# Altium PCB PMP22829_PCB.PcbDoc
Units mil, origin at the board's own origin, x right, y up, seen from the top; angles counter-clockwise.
Board outline 1149 x 492 mil, 4 copper layers (Top Layer, Signal Layer 1, Signal Layer 2, Bottom Layer), stack 61.2 mil thick; 29 components, 17 nets, 67 pads, 32 vias.
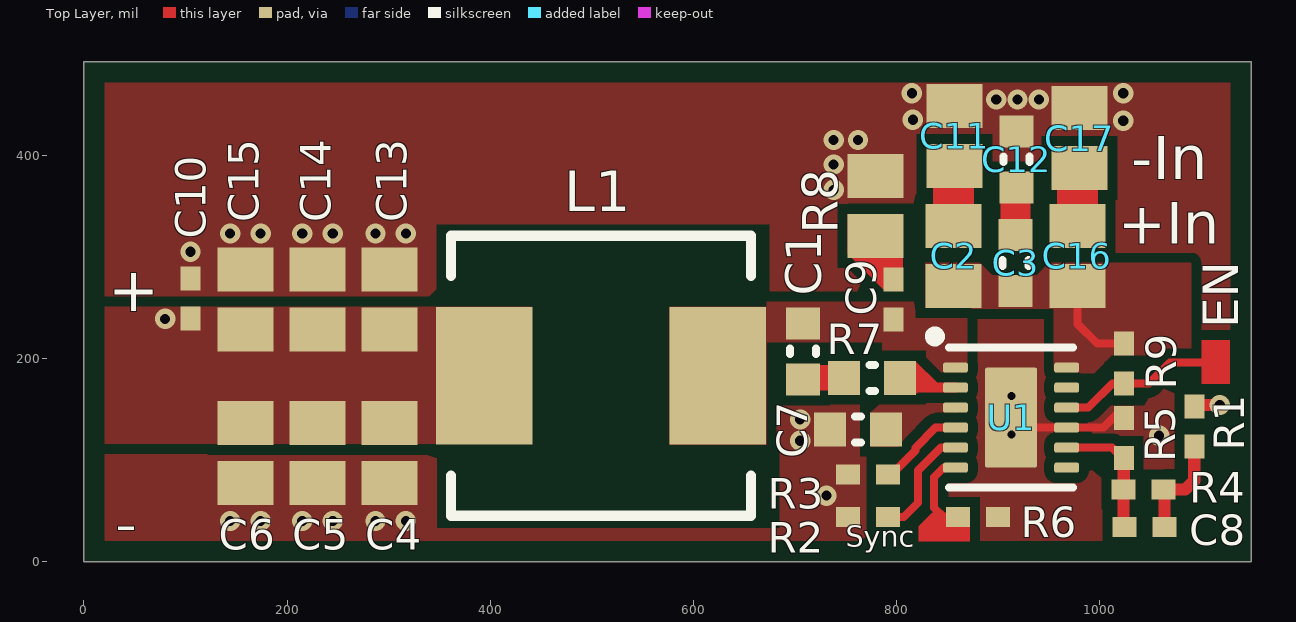
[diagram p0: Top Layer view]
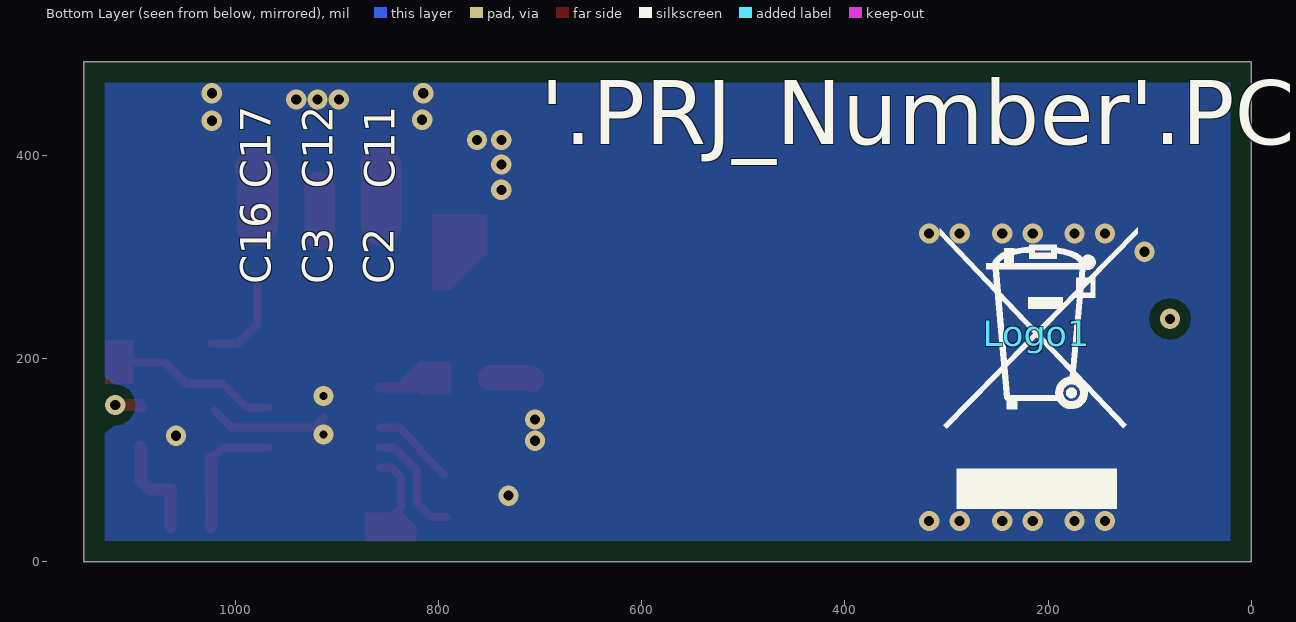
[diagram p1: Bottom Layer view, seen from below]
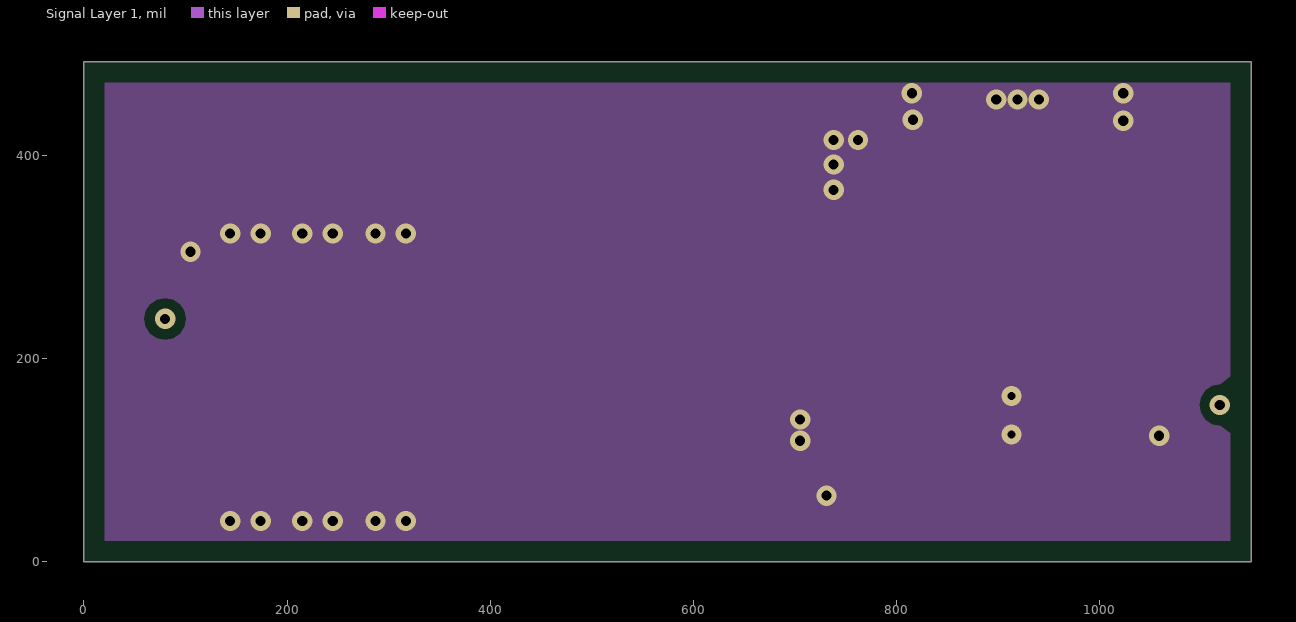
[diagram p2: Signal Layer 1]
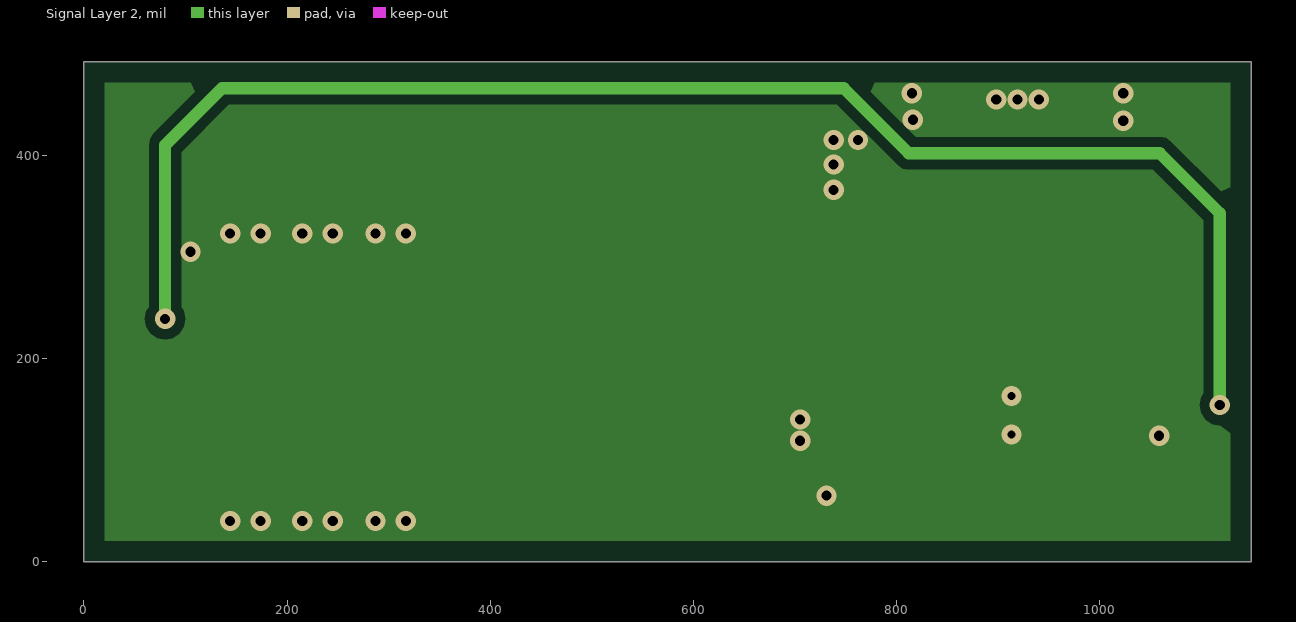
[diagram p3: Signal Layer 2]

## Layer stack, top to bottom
Top Solder: solder mask 0.4, Solder Resist, Dk 3.5
Top Layer: signal copper 1.4
Dielectric 2: dielectric 7.8, Dk 4.2
Signal Layer 1: signal copper 1.4
Dielectric1: core 40, FR-4, Dk 4.8
Signal Layer 2: signal copper 1.4
Dielectric 3: dielectric 7.8, Dk 4.2
Bottom Layer: signal copper 1.4
Bottom Solder: solder mask 0.4, Solder Resist, Dk 3.5

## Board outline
0,0 1149,0 1149,492 0,492

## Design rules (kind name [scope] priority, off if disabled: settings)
AcuteAngle [All] p1: minimum=4.50000000000000E+0001 checktracksonly=FALSE
AssemblyTestPointUsage [All] p1: valid=2
BoardOutlineClearance BoardOutlineClearance_MountingHoles [OnCopper and InComponentClass('Mounting Holes')] p1: gap=39.37 ignorepadtopadclearanceinfootprint=FALSE
BoardOutlineClearance BoardOutlineClearance_Poly [OnCopper and IsPoly] p2: gap=20 ignorepadtopadclearanceinfootprint=FALSE
BoardOutlineClearance [OnCopper and Not InComponentClass('Logo') and not InComponentClass('FiducialMark') and not InRegion(1000,500,4000,800) and not InPoly] p3: gap=20 ignorepadtopadclearanceinfootprint=FALSE
Clearance Clearance_Keepouts [((IsTrack Or IsArc) And Not InPoly) And IsFree and IsKeepOut vs ((IsTrack Or IsArc) And Not InPoly) And IsFree and IsKeepOut] p1: gap=0 ignorepadtopadclearanceinfootprint=FALSE
Clearance Clearance_Poly [InPolygon] p2: gap=10 ignorepadtopadclearanceinfootprint=TRUE
Clearance Clearance_FiducialMark [IsKeepOut and InComponentClass('FiducialMark') vs IsPad and InComponentClass('FiducialMark')] p3: gap=0 ignorepadtopadclearanceinfootprint=FALSE
Clearance [All] p4: gap=7.87 ignorepadtopadclearanceinfootprint=TRUE
ComponentClearance ComponentClearance_Inductors [InComponent('L1') vs InComponent('L2')] p1: gap=-1 collisioncheckmode=3 verticalgap=100000 showdistances=FALSE
ComponentClearance ComponentClearance_MountingHoles_FiducialMarks [InComponentClass('Mounting Holes') vs InComponentClass('FiducialMark')] p2: gap=50 collisioncheckmode=3 verticalgap=10 showdistances=FALSE
ComponentClearance ComponentClearance_Shunt [InComponentClass('Header') vs InComponentClass('Shunt')] p3: gap=0 collisioncheckmode=3 verticalgap=0 showdistances=FALSE
ComponentClearance ComponentClearance_Logo [InComponentClass('Logo')] p4: gap=50 collisioncheckmode=3 verticalgap=10 showdistances=FALSE
ComponentClearance ComponentClearance_ScrewToNut [(HasFootprint('NY PMS 440 0025 PH')) vs (HasFootprint('Keystone_1902C'))] p5: gap=5 collisioncheckmode=3 verticalgap=10 showdistances=FALSE
ComponentClearance ComponentClearance_MountingHoles [InComponentClass('Mounting Holes')] p6: gap=250 collisioncheckmode=3 verticalgap=100000 showdistances=FALSE
ComponentClearance ComponentClearance_SmallPassives [HasFootprint('0201*') or HasFootprint('0402*') or HasFootprint('0508') or HasFootprint('0603*') or HasFootprint('0612') or HasFootprint('0805*') or HasFootprint('0815*') or HasFootprint('0830*') or HasFootprint('1206*') or HasFootprint('1210*') or HasFootprint('1808*') or HasFootprint('1812*') or HasFootprint('1825*') or HasFootprint('2010*') or HasFootprint('2220*') or HasFootprint('2225*') or HasFootprint('2512*') or HasFootprint('2728*') or HasFootprint('3518*') vs HasFootprint('0201*') or HasFootprint('0402*') or HasFootprint('0508') or HasFootprint('0603*') or HasFootprint('0612') or HasFootprint('0805*') or HasFootprint('0815*') or HasFootprint('0830*') or HasFootprint('1206*') or HasFootprint('1210*') or HasFootprint('1808*') or HasFootprint('1812*') or HasFootprint('1825*') or HasFootprint('2010*') or HasFootprint('2220*') or HasFootprint('2225*') or HasFootprint('2512*') or HasFootprint('2728*') or HasFootprint('3518*')] p7: gap=13 collisioncheckmode=3 verticalgap=10 showdistances=FALSE
ComponentClearance ComponentClearance_THtoSMT [IsThruComponent vs IsSMTComponent] p8: gap=40 collisioncheckmode=3 verticalgap=30 showdistances=FALSE
ComponentClearance ComponentClearance_THtoTH [IsThruComponent vs IsThruComponent] p9: gap=25 collisioncheckmode=3 verticalgap=30 showdistances=FALSE
ComponentClearance [All] p10: gap=15 collisioncheckmode=3 verticalgap=10 showdistances=FALSE
DiffPairsRouting [All] p1: maxlimit=100 minlimit=10 mostfreqgap=10 toplayer_minwidth=15 toplayer_maxwidth=15 toplayer_prefwidth=15 midlayer1_minwidth=15 midlayer1_maxwidth=15 midlayer1_prefwidth=15 midlayer2_minwidth=15 midlayer2_maxwidth=15 midlayer2_prefwidth=15 bottomlayer_minwidth=15 bottomlayer_maxwidth=15 bottomlayer_prefwidth=15 maxuncoupledlength=1000
FabricationTestPointUsage TestPointUsage [All] p1: valid=2 allowmultiple=FALSE
FabricationTestpoint Testpoint [All] p1: side=3 testpointundercomponent=TRUE minsize=40 maxsize=100 preferedsize=60 minholesize=0 maxholesize=40 preferedholesize=32 testpointgrid=1 allowsidetop=TRUE allowsidebottom=TRUE usegrid=TRUE gridtolerance=0.01
FanoutControl Fanout_LCC [IsLCC] p1: bgadir=Out bgaviamode=Centered fanoutstyle=Auto fanoutdirection=Alternating viagrid=1 // Fanout_LCC (Default Rule)
FanoutControl Fanout_BGA [IsBGA] p2: bgadir=Out bgaviamode=Centered fanoutstyle=Auto fanoutdirection=Alternating viagrid=1 // Fanout_BGA (Default Rule)
FanoutControl Fanout_Default [All] p4: bgadir=Out bgaviamode=Centered fanoutstyle=Auto fanoutdirection=Alternating viagrid=1 // Fanout_Default (Default Rule)
FanoutControl Fanout_Small [(CompPinCount < 5)] p5: bgadir=Out bgaviamode=Centered fanoutstyle=Auto fanoutdirection=OutThenIn viagrid=1 // Fanout_Small (Default Rule)
HoleSize [All] p1: absolutevalues=TRUE maxlimit=251 minlimit=7.87 maxpercent=80.000 minpercent=20.000
MinimumAnnularRing MinimumAnnularRing_ThermalPadVias [IsVia and InAnyComponent] p1: minimumring=5
MinimumAnnularRing [All] p2: minimumring=5
MinimumSolderMaskSliver MinimumSolderMaskSliver_Logo [InComponentClass('Logo') vs InComponentClass('Logo')] p1: minsoldermaskwidth=0.7
MinimumSolderMaskSliver [All] p2: minsoldermaskwidth=0.2
PlaneClearance [All] p1: clearance=12
PlaneConnect [All] p1: planeconnectstyle=Direct reliefexpansion=10 reliefentries=4 reliefconductorwidth=10 reliefairgap=10
PolygonConnect [All] p1: connectstyle=Direct reliefconductorwidth=10 reliefentries=4 polygonreliefangle="90 Angle" airgapwidth=10
RoutingVias ThermalPadVias [IsVia and InAnyComponent] p1: holewidth=7.87 width=19.68 viastyle="Through Hole" minholewidth=7.87 minwidth=18 maxholewidth=20 maxwidth=30
RoutingVias [All] p2: holewidth=16 width=34 viastyle="Through Hole" minholewidth=7.87 minwidth=18 maxholewidth=40 maxwidth=65
SilkToBoardRegionClearance [Not ((IsComment or IsDesignator) And (Hide <> 'False')) and not InRegion(1000,500,4000,800)] p1:
SilkToSilkClearance SilkToSilkClearance_Pb-FreeLogo [(HasFootprint('Pb-Free_Overlay_Medium') OR HasFootprint('Pb-Free_Overlay_Small')) vs (HasFootprint('Pb-Free_Overlay_Medium') OR HasFootprint('Pb-Free_Overlay_Small'))] p1: silktosilkclearance=0
SilkToSilkClearance [All] p2: silktosilkclearance=2
SilkToSolderMaskClearance SilkToComponentPadClearance [(IsPad or IsFill or IsRegion) and InAnycomponent] p1: minsilkscreentomaskgap=1 clearancetoexposedcopper=TRUE
SilkToSolderMaskClearance "Silk to Solder Mask Opening" [All] p2: minsilkscreentomaskgap=1 clearancetoexposedcopper=FALSE
SolderMaskExpansion [All] p1: expansion=1.97
UnRoutedNet [All] p1: checkbadconnections=TRUE
Width [All] p1: maxlimit=100 minlimit=6 preferedwidth=10 checkconnectedcopper=TRUE
13 further rules are at their usual default settings.

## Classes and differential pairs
component class PMP22829_BlankSheet: C1 C2 C3 C4 C5 C6 C7 C8 C9 C10 C11 C12 C13 C14 C15 C16 C17 R1 R2 R3 R4 R5 R6 R7 R8 R9 U1
component class PMP22829_Hardware: Logo1

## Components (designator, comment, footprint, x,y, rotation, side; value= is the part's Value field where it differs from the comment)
C1 "GCM188R71H224KA64D" 0603L 708,207 r270 top value=0.22uF
C2 "GRM21BR61E226ME44L" 0805L 856,301 r90 top value=22uF
C3 "GCM188R71E474KA64D" 0603L 917,294 r90 top value=0.47uF
C4 "GRM21BR61E226ME44L" 0805L 301,107 r90 top value=22uF
C5 "GRM21BR61E226ME44L" 0805L 230,107 r90 top value=22uF
C6 "GRM21BR61E226ME44L" 0805L 159,107 r90 top value=22uF
C7 "CGA3E1X7R1C105K080AC" 0603L 762,130 r180 top value=1uF
C8 "GCM1555C1H330JA16D" 0402L 1044,34 r180 top value=33pF
C9 "CGA2B2C0G1H102J050BA" 0402L 797,258 r90 top value=1000pF
C10 "GCM155R71H104KE02D" 0402L 105,259 r90 top value=0.1uF
C11 "GRM21BR61E226ME44L" 0805L 857,419 r90 top value=22uF
C12 "GCM188R71E474KA64D" 0603L 918,396 r90 top value=0.47uF
C13 "GRM21BR61E226ME44L" 0805L 301,258 r270 top value=22uF
C14 "GRM21BR61E226ME44L" 0805L 230,258 r270 top value=22uF
C15 "GRM21BR61E226ME44L" 0805L 159,258 r270 top value=22uF
C16 "GRM21BR61E226ME44L" 0805L 978,301 r90 top value=22uF
C17 "GRM21BR61E226ME44L" 0805L 980,417 r90 top value=22uF
L1 "VCMT063T-150MN5TM" VCMT063T-150MN5TM 509,183 r180 top value=15uH
Logo1 "WEEE logo" WEEE_Minimum 211,224.58 r180 bottom
R1 "ERJ-2GE0R00X" 0402L 1093,133 r90 top value=0
R2 "ERJ-2RKF1002X" 0402L 772,44 r0 top value=10.0k
R3 "CRCW040232K4FKED" 0402L 772,86 r0 top value=32.4k
R4 "ERJ-2RKF1003X" 0402L 1043,71 r0 top value=100k
R5 "CRCW040212K1FKED" 0402L 1023.6,121.73 r270 top value=12.1k
R6 "ERJ-2RKF1002X" 0402L 880,44 r180 top value=10.0k
R7 "CRCW06034R70JNEA" 0603L 776,181 r180 top value=4.7
R8 "CRCW08052R00JNEA" 0805L 779,350 r270 top value=2.0
R9 "ERJ-2RKF1003X" 0402L 1024,195 r90 top value=100k
U1 "LM63625DQDRRRQ1" -MFG 912.6,141.79 r0 top

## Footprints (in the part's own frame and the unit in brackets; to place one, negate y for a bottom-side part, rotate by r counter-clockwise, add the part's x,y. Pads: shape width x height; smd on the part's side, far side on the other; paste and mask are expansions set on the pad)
0402L [mm] "0402 from SM-752 data"
  rect 0.6x0.5 smd: 1(-0.5,0) 2(0.5,0)
  body extent -0.55,-0.3 0.55,0.3, height 0.6
0603L [mm] "0603 from SM-752 data"
  rect 0.8x0.85 smd: 1(-0.7,0) 2(0.7,0)
  silkscreen extent -0.07,-0.33 0.07,0.33, body extent -0.87,-0.47 0.87,0.47, height 1
0805L [mm] "0805 from SM-752 data"
  rect 1.1x1.4 smd: 1(-0.75,0) 2(0.75,0)
  body extent -1.1,-0.72 1.1,0.72, height 1.45
-MFG [mm]
  rrect40% 0.62x0.25 smd paste+0 mask+0: 1(-1.39,1.25) 2(-1.39,0.75) 3(-1.39,0.25) 4(-1.39,-0.25) 5(-1.39,-0.75) 6(-1.39,-1.25) 7(1.39,-1.25) 8(1.39,-0.75) 9(1.39,-0.25) 10(1.39,0.25) 11(1.39,0.75) 12(1.39,1.25)
  rrect8% 1.3x2.5 smd paste-1000 mask+0: 13(0,0)
  silkscreen extent -2.03,-1.75 1.55,2.16, body extent -1.8,-1.65 1.8,1.65, height 0.25
VCMT063T-150MN5TM [mil]
  rect 95x135 smd: 1(-115,0) 2(115,0)
  silkscreen extent -148,-138 148,138
WEEE_Minimum [mil] "WEEElie bin"
  silkscreen extent -95,-172 99,104

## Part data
C1: library part CMP-0007145-4, "CAP, CERM, 0.22 uF, 50 V, +/- 10%, X7R, AEC-Q200 Grade 1, 0603", Cap_Case=0603, Manufacturer=MuRata, Supplier Part Number 1=490-5402-1-ND, TempCo=X7R, Tolerance_%=10%, Value1=Unknown, Value2=50V, ValueDisplayed=0.22uF
C2 C4 C5 C6 C11 C13 C14 C15 C16 C17: library part CMP-0008305-2, "CAP, CERM, 22 uF, 25 V, +/- 20%, X5R, 0805", Cap_Case=0805, Manufacturer=MuRata, Supplier Part Number 1=490-10749-1-ND, TempCo=X5R, Tolerance_%=20%, Value1=Unknown, Value2=25V, ValueDisplayed=22uF
C3 C12: library part CMP-0007142-4, "CAP, CERM, 0.47 uF, 25 V, +/- 10%, X7R, AEC-Q200 Grade 1, 0603", Cap_Case=0603, Manufacturer=MuRata, Supplier Part Number 1=490-4776-1-ND, TempCo=X7R, Tolerance_%=10%, Value1=Unknown, Value2=25V, ValueDisplayed=0.47uF
C7: library part CMP-0079607-1, "CAP, CERM, 1 µF, 16 V,+/- 10%, X7R, AEC-Q200 Grade 1, 0603", Cap_Case=0603, Manufacturer=TDK, Supplier Part Number 1=445-12539-1-ND, TempCo=X7R, Tolerance_%=10%, Value2=16V, ValueDisplayed=1µF
C8: library part CMP-0860833-1, "CAP, CERM, 33 pF, 50 V,+/- 5%, C0G/NP0, AEC-Q200 Grade 1, 0402", Cap_Case=0402, Manufacturer=MuRata, TempCo=C0G/NP0, Tolerance_%=5%, Value2=50V, ValueDisplayed=33pF
C9: library part CMP-0006309-2, "CAP, CERM, 1000 pF, 50 V, +/- 5%, C0G/NP0, AEC-Q200 Grade 1, 0402", Cap_Case=0402, Manufacturer=TDK, Supplier Part Number 1=445-6885-1-ND, TempCo=C0G/NP0, Tolerance_%=5%, Value1=Unknown, Value2=50V, ValueDisplayed=1000pF
C10: library part CMP-0006356-2, "CAP, CERM, 0.1 uF, 50 V, +/- 10%, X7R, AEC-Q200 Grade 1, 0402", Cap_Case=0402, Manufacturer=MuRata, Supplier Part Number 1=490-10672-1-ND, TempCo=X7R, Tolerance_%=10%, Value1=Unknown, Value2=50V, ValueDisplayed=0.1uF
L1: Alternate Manufacturer=-, Manufacturer=Cyntec
Logo1: library part CMP-0074769-1
R1: library part CMP-0026992-3, "RES, 0, 5%, 0.1 W, AEC-Q200 Grade 0, 0402", Manufacturer=Panasonic, Power_W=100mW, Supplier Part Number 1=P0.0JCT-ND, TempCo="600 ppm/C", Tolerance_%=5%, Value2=0.1W, Value_Code=0000, ValueDisplayed=0
R2 R6: library part CMP-0026658-1, "RES, 10.0 k, 1%, 0.1 W, 0402", Manufacturer=Panasonic, Power_W=100mW, Supplier Part Number 1=P10.0KLCT-ND, TempCo="100 ppm/C", Tolerance_%=1%, Value2=0.1W, Value_Code=10k0, ValueDisplayed=10.0k
R3: library part CMP-0026294-2, "RES, 32.4 k, 1%, 0.063 W, AEC-Q200 Grade 0, 0402", Manufacturer=Vishay-Dale, Power_W=63mW, Supplier Part Number 1=541-32.4KLCT-ND, TempCo="100 ppm/C", Tolerance_%=1%, Value2=0.063W, Value_Code=32k4, ValueDisplayed=32.4k
R4 R9: library part CMP-0026659-2, "RES, 100 k, 1%, 0.1 W, 0402", Manufacturer=Panasonic, Power_W=100mW, TempCo="100 ppm/C", Tolerance_%=1%, Value2=0.1W, Value_Code=100k
R5: library part CMP-0025991-3, "RES, 12.1 k, 1%, 0.063 W, AEC-Q200 Grade 0, 0402", Manufacturer=Vishay-Dale, Power_W=63mW, Supplier Part Number 1=541-12.1KLCT-ND, TempCo="100 ppm/C", Tolerance_%=1%, Value2=0.063W, Value_Code=12k1, ValueDisplayed=12.1k
R7: library part CMP-0025821-4, "RES, 4.7, 5%, 0.1 W, AEC-Q200 Grade 0, 0603", Manufacturer=Vishay-Dale, Power_W=100mW, Supplier Part Number 1=541-4.7GCT-ND, TempCo="200 ppm/C", Tolerance_%=5%, Value2=0.1W, Value_Code=4R70, ValueDisplayed=4.7
R8: library part CMP-0020518-3, "RES, 2.0, 5%, 0.125 W, AEC-Q200 Grade 0, 0805", Manufacturer=Vishay-Dale, Power_W=125mW, Supplier Part Number 1=541-2.0ACT-ND, TempCo="200 ppm/C", Tolerance_%=5%, Value2=0.125W, Value_Code=2R00, ValueDisplayed=2.0
U1: library part CMP-0088323-1, "3.5-V to 36-V, 2.5-A Automotive Step-down Voltage Converter", Manufacturer="Texas Instruments", Max Supply Voltage=36V, Min Supply Voltage=3.5V, Nominal Supply Current=23uA, Operating Temperature Range="-40°C to +125°C", Output Voltage=1-20V, Switching Frequency=250-2200kHz

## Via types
v1: diameter 20, hole 10, Top Layer to Bottom Layer, tented both sides, 30 vias
v2: diameter 19.68, hole 7.87, Top Layer to Bottom Layer, 2 vias

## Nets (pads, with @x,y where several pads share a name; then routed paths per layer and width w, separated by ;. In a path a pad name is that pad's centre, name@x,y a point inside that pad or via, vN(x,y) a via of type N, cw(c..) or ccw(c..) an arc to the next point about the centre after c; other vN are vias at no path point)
+Vin: C2.1 C3.1 C16.1 R9.2 U1.12 | length 91.4
  Top Layer w8: C16.1 978,234.12 997.43,214.69 R9.2
+Vout: C4.2 C5.2 C6.2 C10.1 C13.2 C14.2 C15.2 L1.2 R1.2 | length 1497.5
  Top Layer w12: R1.2 1094.58,154.27 v1(1118,154.27)
  Signal Layer 2 w12: v1(80,239) 80,410 136,466 748,466 812,402 1059,402 1118,343 v1(1118,154.27)
BST: R7.1 U1.2 | length 23.3
  Top Layer w10: 834.56,171.32 U1.2
EN: R9.1 U1.10 | length 166.1
  Top Layer w8: U1.10 988.63,151.63 1012.32,175.32 R9.1 1048.26,175.32 1068.95,196 1115,196
FB: C8.2 R4.1 R5.2 U1.8 | length 128.7
  Top Layer w8: U1.8 1012.06,112.26 R5.2@1022.91,101.41
  Top Layer w12: R5.2 1023.6,71.28 R4.1 1023.32,35 C8.2
GND: C4.1 C5.1 C6.1 C7.2 C10.2 C11.2 C12.2 C13.1 C14.1 C15.1 C17.2 R2.1 R3.1 R5.1 R6.1 R8.1 U1.9 U1.13 | length 119
  Top Layer w8: U1.13 922.44,131.95 U1.9 1003.51,131.95 R5.1@1020.46,148.9
  other v1: 144,40 174,40 215,40 245,40 287,40 317,40 731,65 705,119 1058.36,124 705,140 105,305 144,323 174,323 215,323 245,323 287,323 317,323 738,366 738,391 738,415 762,415 1023,434 816,435 898,455 919,455 940,455 815,461 1023,461
  other v2: 913,125 913,163
NetC1_2: C1.2 R7.2 | length 41.1
  Top Layer w25: C1.2 709.56,181 R7.2
NetC2_2: C2.2 C11.1 | length 59.4
  Top Layer w40: C2.2 856,388.47 C11.1
NetC3_2: C3.2 C12.1 | length 47.3
  Top Layer w30: C3.2 917,367.44 C12.1
NetC8_1: C8.1 R1.1 R4.2 | length 104.8
  Top Layer w12: C8.1 1063.68,70 R4.2 1084,71 1093,80 R1.1
NetC9_2: C9.2 R8.2
NetC16_2: C16.2 C17.1 | length 57.8
  Top Layer w40: C16.2 978,385.47 C17.1
RT: R3.2 U1.4 | length 83.6
  Top Layer w8: R3.2@794.69,86 794.87,86 818.44,109.58 818.44,111.96 838.43,131.95 U1.4
SW: C1.1 C9.1 L1.1 U1.1
Sync_Mode: R6.2 U1.6 | length 82.1
  Top Layer w8: U1.6 846.34,92.58 836.87,83.11 836.87,53.13 846,44 R6.2
VCC: C7.1 U1.3
VSEL: R2.2 U1.5 | length 113
  Top Layer w8: R2.2 807,44 821,58 821,89.68 843.58,112.26 U1.5
pads on no net: U1.7 U1.11

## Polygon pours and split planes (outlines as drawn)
GND on Top Layer "TOP_LAYER_GND" (solid, remove dead copper, pour order 8): 0,0 0,492 1149,492 1149,0
+Vout on Top Layer "TOP_LAYER_Vout" (solid, remove dead copper, pour order 6): 0,251 441,251 441,116 0,116
+Vin on Top Layer "TOP_LAYER_Vin" (solid, remove dead copper, pour order 4): 994,294 1090,294 1090,203 1011.83,203 994.56,185.73 954.87,185.73 954.87,248 953.87,249 828,249 828,294 882,294 894,282 938,282 950,294
SW on Top Layer "TOP_LAYER_SW" (solid, remove dead copper, pour order 2): 672,256 672,251 576,251 576,115 672,115 672,216 786,216 786,208 829,208 829,200 843,186 869.46,186 869.46,256
VCC on Top Layer "TOP_LAYER_VCC" (solid, remove dead copper, pour order 0): 868,147 838,147 804,113 775,113 775,156 868,156
GND on Signal Layer 1 "SIGNAL_LAYER_1_GND" (solid, remove dead copper, pour order 10): 0,0 0,492 1149,492 1149,0
GND on Bottom Layer "BOTTOM_LAYER_GND" (solid, remove dead copper, pour order 18): 0,0 0,492 1149,492 1149,0
GND on Signal Layer 2 "SIGNAL_LAYER_2_GND" (solid, remove dead copper, pour order 16): 0,0 0,492 1149,492 1149,0

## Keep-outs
Keep-Out Layer:
  text ".Layer_Name" at 687,-858.49 h60

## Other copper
Top Layer:
  rectangle net EN: 1100,175 1128,218
  pour cut-out: 347.22,108 444,108 444,258 347.02,258 346.92,332 674,332 675,333 675,258 567,258 567,108 685,108 685,33 347.33,33
  region net NetC9_2: 752,342 806,342 806,267 788,267 752,303
  region net BST: 859,167 821,167 819,165 788,165 788,197 819,197 840,176 859,176
  region net Sync_Mode: 822,20 822,35 835,48 872,48 872,20
  text ".Layer_Name" at 687,-858.49 h60
Bottom Layer:
  text ".Layer_Name" at 687,-858.49 h60

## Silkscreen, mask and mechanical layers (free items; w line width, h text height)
Top Overlay:
  text "-In" at 1031,362 h72.83
  text "+In" at 1018,299 h70
  text "+" at 24,232 h75
  text "EN" at 1136,230 h35 r90
  text "Sync" at 750,8 h35
  text "-" at 31,3 h75
  text ".Layer_Name" at 687,-858.49 h60
Bottom Overlay:
  text "'.PRJ_Number'.PCB_Rev" at 700,390 h108.27
  text ".Layer_Name" at 687,-858.49 h60
Top Paste:
  text ".Layer_Name" at 687,-858.49 h60
Bottom Paste:
  text ".Layer_Name" at 687,-858.49 h60
Top Solder:
  region: 1090,234 1090,294 1013,294 1013,234
  region: 1128,412 1128,472 1037,472 1037,412
  region: 20,224 20,146 120,146 120,224
  region: 20,96 20,28 120,28 120,96
  region: 822,20 822,35 835,48 872,48 872,20
  text ".Layer_Name" at 687,-858.49 h60
  text ".Layer_Name" at 687,-858.49 h60
Bottom Solder:
  text ".Layer_Name" at 687,-858.49 h60
Drill Guide:
  text ".Layer_Name" at 687,-858.49 h60
M1 Board Outline:
  the board outline again, w10
  text ".Layer_Name" at 687,-858.49 h60
M2 Board Dimensions:
  rectangle: 110,-275 235,-150
  rectangle: 235,-400 610,-275
  lines w7: 110,-275 1110,-275 ; 235,-400 235,-150 ; 360,-400 360,-150 ; 610,-400 610,-150 ; 860,-400 860,-150 ; 110,-400 1110,-400 1110,-150 110,-150 110,-400
  text ".Layer_Name" at 687,-858.49 h60
M3 3D STEP Top:
  text ".Layer_Name" at 687,-858.49 h60
M4 3D STEP Bottom:
  text ".Layer_Name" at 687,-858.49 h60
M5 Assembly Top:
  lines w10: -182,-930.17 6418,-930.17 ; -182,-726.83 6420,-726.83 ; -182,-523.5 -182,-1133.5 3823,-1133.5 6420,-1133.5 6420,-523.5 -181.5,-523.5 -181.5,-1133.5 1394,-1133.5 ; 2283,-1133.5 2283,-523.5 ; 3550,-726.83 3550,-523.5 ; 4390,-726.83 4390,-523.5 ; 5012,-1140 5012,-937.17
  text "COMPONENTS MARKED 'DNP' SHOULD NOT BE POPULATED." at 1263.5,-318.5 h60
  text "ASSEMBLY VARIANT:" at 1263,-434 h60
  text ".VariantName" at 2299,-434 h60
  text "PCB VIEWED FROM TOP SIDE" at -118.5,-655.67 h60
  text "BOARD #:" at 2358,-655.67 h60
  text ".PRJ_Number" at 2903.5,-655.67 h60
  text "REV:" at 3748,-655.67 h60
  text ".PCB_Rev" at 4039.5,-655.67 h60
  text "SVN REV:" at 4586,-655.67 h60
  text ".VersionControl_RevNumber" at 5092,-655.67 h60
  text "TID #:" at 2358,-859 h60
  text ".TID" at 2903.5,-859 h60
  text "PLOT NAME =" at -118.5,-1064.34 h60
  text ".plot_File_Name" at 687,-1064.34 h60
  text "GENERATED    :" at 2360,-1064.34 h60
  text ".Print_Date" at 3229.5,-1064.34 h60
  text ".Print_Time" at 3958.5,-1064.34 h60
  text "TEXAS INSTRUMENTS" at 5223,-1064.34 h60
M6 Assembly Bottom:
  lines w10: -182.5,-727.33 6419.5,-727.33 ; -180.5,-930.67 6419.5,-930.67 ; 1225.5,-1140.5 1225.5,-937.67 ; 1847.5,-727.33 1847.5,-524 ; 2687.5,-727.33 2687.5,-524 ; 3954.5,-1134 3954.5,-524 ; 4843.5,-1134 6419,-1134 6419,-524 -182.5,-524 -182.5,-1134 2414.5,-1134 6419.5,-1134 6419.5,-524
  text "COMPONENTS MARKED 'DNP' SHOULD NOT BE POPULATED." at 6212,-318 h60
  text ".VariantName" at 5168,-434 h60
  text "ASSEMBLY VARIANT:" at 6207,-434 h60
  text ".VersionControl_RevNumber" at 1145.5,-656.17 h60
  text "SVN REV:" at 1651.5,-656.17 h60
  text ".PCB_Rev" at 2198,-656.17 h60
  text "REV:" at 2489.5,-656.17 h60
  text ".PRJ_Number" at 3334,-656.17 h60
  text "BOARD #:" at 3879.5,-656.17 h60
  text "PCB VIEWED FROM BOTTOM SIDE" at 6356,-656.17 h60
  text ".TID" at 3334,-859.5 h60
  text "TID #:" at 3879.5,-859.5 h60
  text "TEXAS INSTRUMENTS" at 1014.5,-1064.84 h60
  text ".Print_Time" at 2279,-1064.84 h60
  text ".Print_Date" at 3008,-1064.84 h60
  text "GENERATED    :" at 3877.5,-1064.84 h60
  text ".plot_File_Name" at 5550.5,-1064.84 h60
  text "PLOT NAME =" at 6356,-1064.84 h60
M9 Title Sheet:
  drawing of 57 lines, arcs and shapes, not listed
  text "1" at 849.84,8036.5 h70
  text "2" at 3345.5,8036.5 h70
  text "3" at 5834.84,8036.5 h70
  text "4" at 8341.51,8036.5 h70
  text "5" at 10840.5,8036.5 h70
  text "6" at 13345.5,8036.5 h70
  text "A" at -306.5,6893.5 h70
  text "A" at 14493.5,6893.5 h70
  text "B" at -306.5,4513.5 h70
  text "B" at 14493.5,4513.5 h70
  text "C" at -306.5,2138.5 h70
  text "C" at 14493.5,2138.5 h70
  text "PROJECT TITLE:" at 11453.5,277.5 h45
  text ".PRJ_Title" at 11503.5,144.17 h70
  text "DESIGNED FOR:" at 11453.5,-23.5 h45
  text ".PRJ_Customer" at 11503.5,-163.5 h70
  text "D" at -306.5,-231.5 h70
  text "D" at 14493.5,-231.5 h70
  text "FILE NAME:" at 11453.5,-323.5 h45
  text ".PCB_File_Name_No_Path" at 11503.5,-443.5 h70
  text "Texas Instruments (TI) and/or its licensors do not warrant the accuracy or completeness of this specification" at 6484,-605.34 h45
  text "ENGINEER:" at 11453.5,-613.5 h45
  text "LAYOUT BY:" at 12958.5,-613.5 h45
  text "or any information contained therein. TI and/or its licensors do not warrant that this design will meet" at 6439.01,-718 h45
  text ".PRJ_Engineer" at 11503.5,-768.49 h70
  text ".PCB_Layout" at 13009,-768.49 h70
  text "the specifications, will be suitable for your application or fit for any particular purpose, or will operate in" at 6439.01,-830.67 h45
  text ".Layer_Name" at 687,-858.49 h60
  text "ALTIUM DESIGNER VERSION:" at 12958.5,-923.5 h45
  text "an implementation. TI and/or its licensors do not warrant that the design is production worthy. You should" at 6439.01,-943.33 h45
  text "completely validate and test your design implementation to confirm the system functionality for your application." at 6484,-1056 h45
  text ".print_Scale" at 11503.5,-1056.83 h70
  text ".Application_BuildNumber" at 13009,-1056.83 h70
  text "1" at 849.84,-1263.5 h70
  text "2" at 3345.5,-1263.5 h70
  text "3" at 5834.84,-1263.5 h70
  text "4" at 8341.51,-1263.5 h70
  text "5" at 10840.5,-1263.5 h70
  text "6" at 13345.5,-1263.5 h70
M10 Fab Notes:
  drawing of 189 lines, arcs and shapes, not listed
  text "DESIGN INFORMATION" at 12492.02,6356.17 h60
  text "MIN. TRACK WIDTH:" at 11847.46,6224.05 h60
  text "6" at 12943.7,6224.05 h60
  text "MIL" at 13098.46,6224.05 h60
  text "MIN. CLEARANCE:" at 11847.46,6099.92 h60
  text "0.2" at 12883.7,6099.93 h60
  text "mm" at 13098.46,6099.92 h60
  text "MIN. VIA PAD SIZE:" at 11847.46,5975.8 h60
  text "20" at 12913.71,5975.8 h60
  text "MIL" at 13098.46,5975.8 h60
  text "0.127mm (5MIL)" at 12542.46,5845.9 h60
  text "MINIMUM ANNULAR RING" at 11518.23,5837.67 h60
  text "EXTERNAL" at 13250.46,5837.67 h60
  text "PER" at 11718.23,5727.55 h60
  text "IPC-D-275 CLASS 2 LEVEL C" at 11938.23,5727.54 h60
  text "MIL, HOLES" at 13426.46,5627.07 h60
  text "+/-" at 13034,5618.48 h60
  text "+/-" at 13888,5618.48 h60
  text "REGISTRATION TOLERANCES:" at 11518.23,5617.42 h60
  text "METAL" at 12718,5617.42 h60
  text "5" at 13294.2,5617.42 h60
  text "3" at 14127.2,5617.42 h60
  text "MIL" at 14243.46,5617.42 h60
  text "HOLE SIZE TOLERANCE (UNLESS OTHERWISE SPECIFIED):" at 11518.23,5519.1 h60
  text "+/-" at 13888,5516.23 h60
  text "3" at 14127.2,5515.17 h60
  text "MIL" at 14243.46,5515.17 h60
  text "MATERIAL:" at 11443.46,5377.52 h60
  text "FR-4 High Tg" at 12429.9,5249 h60
  text "X" at 12285.46,5241.01 h60
  text "FR-408" at 11864.46,5236.49 h60
  text "OTHER" at 13352.46,5236.49 h60
  text "62 MIL (1.6mm) +/-10%" at 12184.56,5093.46 h60
  text "X" at 12064.46,5091.01 h60
  text "THICKNESS:" at 11518.23,5085.24 h60
  text "OTHER" at 13469.46,5085.24 h60
  text "TOLERANCE:" at 11518.23,4946.92 h60
  text "X" at 12366.46,4946.92 h60
  text "ANSI IPC-6012 TYPE 3 CLASS 2" at 12544.48,4946.92 h60
  text "OTHER +/-" at 12544.46,4802.73 h60
  text "BOW & TWIST:" at 11518.23,4657.54 h60
  text "X" at 12366.46,4657.54 h60
  text "ANSI IPC-6012 TYPE 3 CLASS 2" at 12544.48,4657.54 h60
  text "OTHER +/-" at 12544.46,4510.85 h60
  text "DRILLING:" at 11443.46,4380.23 h60
  text "NC_DRILL FILES" at 13204.46,4275.04 h60
  text "REFERENCE:" at 11518.23,4271.1 h60
  text "X" at 12175.46,4271.01 h60
  text "AS SHOWN" at 12353.46,4271.1 h60
  text "X" at 13076.46,4271.1 h60
  text "OTHER" at 13502.46,4128.85 h60
  text "PTH COPPER THICKNESS:" at 11517.91,4125.32 h60
  text "X" at 12657.14,4125.32 h60
  text "20-30 um" at 12785.14,4125.32 h60
  text "BOARD FINISH:" at 11443.46,3977.73 h60
  text "SILKSCREEN:" at 11598.68,3867.6 h60
  text "X" at 12556.46,3867.6 h60
  text "TOP" at 12673.46,3867.6 h60
  text "X" at 13066.46,3867.6 h60
  text "BOTTOM" at 13184.46,3867.6 h60
  text "SILKSCREEN COLOR:" at 11598.68,3712.41 h60
  text "X" at 12555.46,3712.41 h60
  text "WHITE" at 12673.46,3712.41 h60
  text "OTHER" at 13184.46,3712.41 h60
  text "X" at 12686.46,3568.96 h60
  text "GREEN" at 12804.46,3568.96 h60
  text "OTHER" at 13422.46,3568.96 h60
  text "SOLDER RESIST COLOR:" at 11598.68,3562.1 h60
  text "X" at 12686.46,3414.71 h60
  text "MATTE" at 12804.46,3414.71 h60
  text "SEMI-GLOSS" at 13422,3414.07 h60
  text "IMMERSION GOLD (ENIG)" at 12504.46,3241.94 h60
  text "ENEPIG" at 13842,3234.72 h60
  text "SURFACE FINISH:" at 11443.46,3233.72 h60
  text "X" at 12326.46,3233.72 h60
  text "IMM. TIN/SILVER OR EQUIV" at 11773,3096.4 h60
  text "OTHER" at 13204.46,3092.47 h60
  text "ARRAY/PANEL:" at 11443.46,2937.09 h60
  text "X" at 12321,2934 h60
  text "CUT AND TRIM PER M1 BOARD OUTLINE" at 12504.46,2928.87 h60
  text "N.C. ROUTE" at 12504.46,2792.9 h60
  text "V. SCORE" at 13370.46,2792.9 h60
  text "CERTIFICATION:" at 11443.46,2663.77 h60
  text "MATERIALS AND WORKMANSHIP FOR ALL PCBS" at 12168.46,2663.77 h60
  text "TO MEET OR EXCEED THE REQUIREMENTS OF:" at 12168.46,2569.71 h60
  text "X" at 11805.97,2441.08 h60
  text "ANSI IPC-A-600F CLASS ->" at 11933.96,2441.08 h60
  text "X" at 13581.97,2441.08 h60
  text "2" at 13691.96,2441.08 h60
  text "1" at 13376.96,2439.58 h60
  text "3" at 14045.96,2439.58 h60
  text "X" at 12617.97,2293.39 h60
  text "RoHS" at 12745.96,2293.39 h60
  text "OTHER" at 13390.36,2293.39 h60
  text "PER ORDER" at 13787.42,2293.39 h60
  text "ALL BOARDS MUST MEET OR EXCEED UL94-V0 REQUIREMENTS." at 11471,2139.57 h60
  text "PCB MUST BEAR THE UL94V-0 UL REGISTERED MATERIAL ID NUMBER" at 11471,2023.5 h60
  text "ADDITIONAL REQUIREMENTS:" at 11443.46,1854.08 h60
  text "MICROSECTION:" at 11518.23,1746.95 h60
  text "YES" at 12423.96,1746.95 h60
  text "REQUIRED" at 13285.46,1602.62 h60
  text "BARE BOARD ELEC. TEST:" at 11518.23,1599.76 h60
  text "NONE" at 12823.96,1599.76 h60
  text "X" at 13167.46,1599.76 h60
  text "PER ORDER" at 13877.46,1599.76 h60
  text "XX MIL VIAS REQUIRE NON-CONDUCTIVE FILL AND PLANARIZE" at 11686.38,1394.82 h59
  text "XX MIL VIAS REQUIRE CONDUCTIVE FILL AND PLANARIZE" at 11694.38,1290.84 h60
  text "OUTER XX MIL TRACES REQUIRE 50 OHM SINGLE-ENDED IMPEDANCE" at 11693.39,1127.46 h58
  text "LAYER 2 & 3 (INNER LAYERS) XX MIL WIDE, XX MIL SPACE / TRACES REQUIRE 100 OHM DIFFERENTIAL IMPEDANCE" at 11685.39,891.74 h60
  text ".Layer_Name" at 687,-858.49 h60
M11 Gerber Information:
  lines w10: -182,-930.17 6418,-930.17 ; -182,-726.83 6420,-726.83 ; -182,-523.5 -182,-1133.5 3823,-1133.5 6420,-1133.5 6420,-523.5 -181.5,-523.5 -181.5,-1133.5 1394,-1133.5 ; 2283,-1133.5 2283,-523.5 ; 3550,-726.83 3550,-523.5 ; 4390,-726.83 4390,-523.5 ; 5012,-1140 5012,-937.17
  text "ALL ARTWORK VIEWED FROM TOP SIDE" at -118.5,-655.67 h60
  text "BOARD #:" at 2358,-655.67 h60
  text ".PRJ_Number" at 2903.5,-655.67 h60
  text "REV:" at 3748,-655.67 h60
  text ".PCB_Rev" at 4039.5,-655.67 h60
  text "SVN REV:" at 4586,-655.67 h60
  text ".VersionControl_RevNumber" at 5092,-655.67 h60
  text "LAYER NAME =" at -118.5,-858.49 h60
  text "TID #:" at 2358,-859 h60
  text ".TID" at 2903.5,-859 h60
  text "PLOT NAME =" at -118.5,-1064.34 h60
  text ".plot_File_Name" at 687,-1064.34 h60
  text "GENERATED    :" at 2360,-1064.34 h60
  text ".Print_Date" at 3229.5,-1064.34 h60
  text ".Print_Time" at 3958.5,-1064.34 h60
  text "TEXAS INSTRUMENTS" at 5223,-1064.34 h60
M12 Stackup:
  drawing of 295 lines, arcs and shapes, not listed
  text "Layer" at 6133.35,6245.5 h60
  text "Name" at 6543.26,6245.5 h60
  text "Material" at 7483,6245.5 h60
  text "Thickness" at 8342.77,6245.5 h60
  text "Constant" at 8992.6,6245.5 h60
  text "Board Layer Stack" at 9562.46,6245.5 h60
  text "1" at 6133.35,6125.5 h60
  text "Top Overlay" at 6543.26,6125.5 h60
  text "2" at 6133.35,6005.5 h60
  text "Top Solder" at 6543.26,6005.5 h60
  text "Solder Resist" at 7483,6005.5 h60
  text "0.40mil" at 8342.77,6005.5 h60
  text "3.5" at 8992.6,6005.5 h60
  text "3" at 6133.35,5885.5 h60
  text "Top Layer" at 6543.26,5885.5 h60
  text "Copper" at 7483,5885.5 h60
  text "1.40mil" at 8342.77,5885.5 h60
  text "4" at 6133.35,5765.5 h60
  text "Dielectric 2" at 6543.26,5765.5 h60
  text "7.80mil" at 8342.77,5765.5 h60
  text "4.2" at 8992.6,5765.5 h60
  text "5" at 6133.35,5645.5 h60
  text "Signal Layer 1" at 6543.26,5645.5 h60
  text "Copper" at 7483,5645.5 h60
  text "1.40mil" at 8342.77,5645.5 h60
  text "6" at 6133.35,5525.5 h60
  text "Dielectric1" at 6543.26,5525.5 h60
  text "FR-4" at 7483,5525.5 h60
  text "40.00mil" at 8342.77,5525.5 h60
  text "4.8" at 8992.6,5525.5 h60
  text "7" at 6133.35,5405.5 h60
  text "Signal Layer 2" at 6543.26,5405.5 h60
  text "Copper" at 7483,5405.5 h60
  text "1.40mil" at 8342.77,5405.5 h60
  text "8" at 6133.35,5285.5 h60
  text "Dielectric 3" at 6543.26,5285.5 h60
  text "7.80mil" at 8342.77,5285.5 h60
  text "4.2" at 8992.6,5285.5 h60
  text "9" at 6133.35,5165.5 h60
  text "Bottom Layer" at 6543.26,5165.5 h60
  text "Copper" at 7483,5165.5 h60
  text "1.40mil" at 8342.77,5165.5 h60
  text "10" at 6133.35,5045.5 h60
  text "Bottom Solder" at 6543.26,5045.5 h60
  text "Solder Resist" at 7483,5045.5 h60
  text "0.40mil" at 8342.77,5045.5 h60
  text "3.5" at 8992.6,5045.5 h60
  text "11" at 6133.35,4925.5 h60
  text "Bottom Overlay" at 6543.26,4925.5 h60
  text ".Layer_Name" at 687,-858.49 h60
M13 Component Bodies Top:
  text ".Layer_Name" at 687,-858.49 h60
M14 Component Bodies Bottom:
  text ".Layer_Name" at 687,-858.49 h60
M15 Courtyards Top:
  text ".Layer_Name" at 687,-858.49 h60
M16 Courtyards Bottom:
  text ".Layer_Name" at 687,-858.49 h60
Drill Drawing:
  circle w10: c2473.72,719.96 r27.63
  lines w10: 2446.09,816.66 2501.34,816.66 2501.34,871.91 2446.09,871.91 2446.09,816.66
  lines w12: 2396,655.04 5627.49,655.04 ; 2396,903.68 5627.49,903.68 ; 2733.86,530.72 2733.86,1028 ; 3065.86,530.72 3065.86,1028 ; 3702.43,530.72 3702.43,1028 ; 3961.57,530.72 3961.57,1028 ; 4336.72,530.72 4336.72,1028 ; 5061.05,530.72 5061.05,1028 ; 2396,530.72 5627.49,530.72 5627.49,1028 2396,1028 2396,530.72
  text "Symbol" at 2470.59,940.98 h72
  text "Quantity" at 2771.16,940.98 h72
  text "Finished Hole Size" at 3103.16,940.98 h72
  text "Plated" at 3739.72,940.98 h72
  text "Hole Type" at 3998.86,940.98 h72
  text "Drill Layer Pair" at 4374.02,940.98 h72
  text "Hole Tolerance" at 5098.35,940.98 h72
  text "2" at 2771.16,816.66 h60
  text "7.87mil (0.200mm)" at 3103.16,816.66 h60
  text "PTH" at 3739.72,816.66 h60
  text "Round" at 3998.86,816.66 h60
  text "Top Layer - Bottom Layer" at 4374.02,816.66 h60
  text "30" at 2771.16,692.34 h60
  text "10.00mil (0.254mm)" at 3103.16,692.34 h60
  text "PTH" at 3739.72,692.34 h60
  text "Round" at 3998.86,692.34 h60
  text "Top Layer - Bottom Layer" at 4374.02,692.34 h60
  text "32 Total" at 2771.16,568.02 h60
  text ".Layer_Name" at 687,-858.49 h60
M17 Embedded Cavity:
  text ".Layer_Name" at 687,-858.49 h60
M18 Embedded Assembly:
  text ".Layer_Name" at 687,-858.49 h60
M19 Embedded Keepout:
  text ".Layer_Name" at 687,-858.49 h60

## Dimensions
110,-400 to 1110,-400 on M2 Board Dimensions
110,0 to 0,492 on M2 Board Dimensions
0,0 to 1149,0 on M2 Board Dimensions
